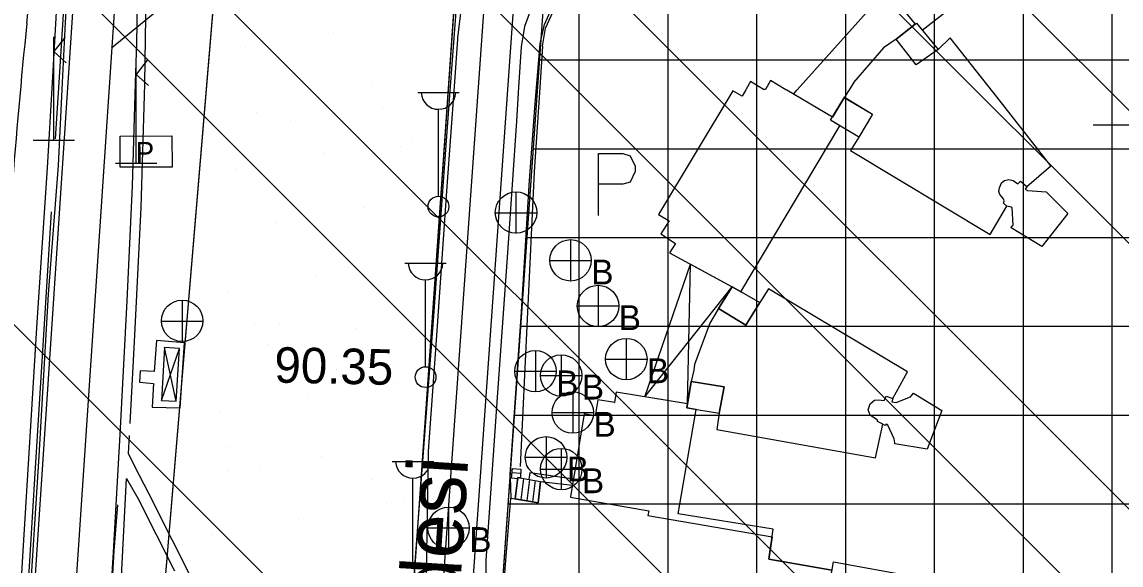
# Model space of a CAD drawing. Extents: x 417995 to 421451, y 4454518 to 4458015.
# Drawn here: x 420306.6 to 420492.2, y 4456425.7 to 4456517.4 of the extents above; entities that cross this region are included whole.
import ezdxf

# ---------------------------------------------------------------- set-up
doc = ezdxf.new("R2010")
doc.units = 0
for name, color, linetype in [('ADAKENARI', 7, 'Continuous'), ('B_Betonzemin', 7, 'Continuous'), ('B_Imalat', 7, 'Continuous'), ('B_Merdiven', 7, 'Continuous'), ('B_Sundurma', 7, 'Continuous'), ('B_Teras', 7, 'Continuous'), ('KALDIRIM_FAT', 7, 'Continuous'), ('P_Grid', 7, 'Continuous'), ('PL_AYA_PARK_DINLENME', 7, 'Continuous'), ('PL_TİCARET', 7, 'Continuous'), ('RAYLI_TOPLU_TAŞIMA_HATTI', 7, 'Continuous'), ('S_Cad_Sok_Lambasi', 7, 'Continuous'), ('S_Kara_Demy_Trafik_Sinyal', 7, 'Continuous'), ('S_Otopark', 7, 'Continuous'), ('S_Pano', 7, 'Continuous'), ('S_Rogar_Kapagi', 7, 'Continuous'), ('S_Rogar_Kapagi_Buski', 7, 'Continuous'), ('Sinir_Duvar_tek_tarafa_ait', 7, 'Continuous'), ('Sinir_Ist_Duvari', 7, 'Continuous'), ('Sinir_Parmaklik_bir_taraf', 7, 'Continuous'), ('Sinir_Tel_bir_taraf', 7, 'Continuous'), ('SN_TR_SIVILASMA', 7, 'Continuous'), ('TRFAT_PARKALANI', 7, 'Continuous'), ('TRFAT_TİCARET', 7, 'Continuous'), ('Y_Cadde_Yol', 7, 'Continuous'), ('Y_Kot_Noktasi', 7, 'Continuous'), ('Yol_Insaat', 7, 'Continuous'), ('Yol_Kaldirim_kenari_bordurtasi', 7, 'Continuous'), ('Yol_Sose', 7, 'Continuous')]:
    doc.layers.add(name, color=color, linetype=linetype)

msp = doc.modelspace()

# ---------------------------------------------------------------- linework, layer by layer
at = {"layer": 'ADAKENARI'}
for p, q in [((420327.09, 4456379.2), (420340.63, 4456540.91)), ((420380.73, 4456537.18), (420369.47, 4456376.76)), ((420385.69, 4456393.42), (420394.63, 4456520.03))]:
    msp.add_line(p, q, dxfattribs=at)
at = {"layer": 'B_Betonzemin'}
for points in [[(420326.52, 4456458.44), (420326.41, 4456456.54), (420328.76, 4456456.33), (420328.56, 4456452.31), (420333.29, 4456452.21), (420334.02, 4456463.18), (420329.28, 4456463.58)], [(420329.28, 4456463.58), (420328.9, 4456458.36), (420326.52, 4456458.44)]]:
    msp.add_lwpolyline(points, dxfattribs=at)
at = {"layer": 'B_Imalat'}
msp.add_lwpolyline([(420449.68, 4456526.48), (420457.39, 4456517.01), (420454.19, 4456514.51), (420452.09, 4456513), (420446.99, 4456507.16), (420446.99, 4456507.13), (420446.19, 4456505.84), (420446.14, 4456505.77), (420445.47, 4456504.69), (420443.45, 4456501.3), (420435.71, 4456505.88), (420435.58, 4456505.95), (420432.97, 4456507.5), (420432.12, 4456505.99), (420431.8, 4456505.99), (420429.58, 4456507.36), (420428.85, 4456506.02), (420428.81, 4456505.95), (420428.22, 4456504.87), (420426.63, 4456505.75), (420414.08, 4456484.89), (420415.86, 4456483.82), (420414.44, 4456481.6), (420416.91, 4456479.96), (420415.94, 4456478.41), (420426.51, 4456472.66), (420424.18, 4456469), (420422.72, 4456466.54), (420422.72, 4456466.54), (420420.12, 4456459.55), (420420.13, 4456459.51), (420420.02, 4456458.59), (420419.59, 4456456.66), (420418.98, 4456452.9), (420406.93, 4456454.89), (420406.65, 4456453.14), (420406.66, 4456453.1), (420403.81, 4456453.55), (420403.36, 4456450.85), (420401.52, 4456451.18), (420401.52, 4456451.18), (420399.2, 4456437.18), (420399.2, 4456437.1), (420412.42, 4456434.83), (420412.26, 4456434.03), (420412.26, 4456434.03), (420433.24, 4456430.4), (420432.7, 4456426.66), (420443.36, 4456424.79)], dxfattribs=at)
at = {"layer": 'B_Merdiven'}
for p, q in [((420389.35, 4456441.3), (420390.77, 4456441.2)), ((420389.91, 4456436.84), (420390.36, 4456440.46)), ((420390.89, 4456436.67), (420391.34, 4456440.28)), ((420391.88, 4456436.49), (420392.33, 4456440.1)), ((420392.86, 4456436.32), (420393.31, 4456439.92))]:
    msp.add_line(p, q, dxfattribs=at)
for points in [[(420389.23, 4456440.31), (420389.42, 4456441.97), (420390.8, 4456441.84), (420390.73, 4456440.39), (420390.32, 4456440.47), (420390.29, 4456440.23)], [(420389.86, 4456436.85), (420390.32, 4456440.47), (420394.12, 4456439.78), (420393.71, 4456436.17)]]:
    msp.add_lwpolyline(points, close=True, dxfattribs=at)
at = {"layer": 'B_Sundurma'}
for p, q in [((420418.98, 4456452.9), (420419.48, 4456476.48)), ((420411.75, 4456454.09), (420426.51, 4456472.66)), ((420332.62, 4456453.32), (420330.63, 4456462.43)), ((420330.11, 4456453.44), (420333.16, 4456462.24))]:
    msp.add_line(p, q, dxfattribs=at)
for points in [[(420419.48, 4456476.48), (420426.51, 4456472.66), (420424.18, 4456469), (420422.72, 4456466.54), (420420.12, 4456459.55), (420420.13, 4456459.51), (420420.02, 4456458.59), (420419.59, 4456456.66), (420418.98, 4456452.9), (420411.75, 4456454.09)], [(420330.63, 4456462.43), (420330.11, 4456453.44), (420332.62, 4456453.32), (420333.16, 4456462.24)]]:
    msp.add_lwpolyline(points, close=True, dxfattribs=at)
at = {"layer": 'B_Teras'}
msp.add_lwpolyline([(420443.36, 4456424.79), (420432.7, 4456426.66), (420432.7, 4456426.66), (420433.43, 4456431.73), (420417.38, 4456434.33), (420417.38, 4456434.33), (420420.43, 4456451.96), (420418.87, 4456452.21), (420419.59, 4456456.66), (420425.13, 4456455.74), (420424.3, 4456451.34), (420423.92, 4456448.55), (420450.74, 4456443.77), (420450.74, 4456443.77), (420451.97, 4456449.44), (420451.05, 4456449.89), (420451.07, 4456450.12), (420449.82, 4456450.95), (420449.47, 4456451.86), (420449.8, 4456452.91), (420450.57, 4456453.5), (420451.18, 4456453.58), (420452.17, 4456453.44), (420452.52, 4456454.18), (420453.62, 4456453.82), (420456.14, 4456458.31), (420432.62, 4456472.29), (420432.62, 4456472.29), (420431.18, 4456470), (420428.84, 4456466.19), (420424.18, 4456469), (420426.51, 4456472.66), (420427.97, 4456471.83), (420444.68, 4456499.86), (420443.14, 4456500.78), (420445.47, 4456504.69), (420450.18, 4456501.81), (420447.88, 4456497.96), (420446.51, 4456495.68), (420470.07, 4456481.51), (420470.07, 4456481.51), (420472.92, 4456486.26), (420472.34, 4456486.81), (420472.46, 4456487.21), (420472.36, 4456487.52), (420471.72, 4456488.25), (420471.55, 4456488.76), (420471.65, 4456489.4), (420472.01, 4456490.24), (420472.51, 4456490.63), (420473.23, 4456490.78), (420473.97, 4456490.59), (420474.74, 4456490.05), (420475.21, 4456490.52), (420476.27, 4456489.62), (420480.32, 4456493.09), (420470.58, 4456505.51), (420470.53, 4456505.58), (420463.35, 4456514.74), (420461.32, 4456512.73), (420457.57, 4456510.15), (420454.19, 4456514.51), (420457.63, 4456517.2), (420458.62, 4456516.02), (420484.26, 4456536.08)], dxfattribs=at)
for points in [[(420454.19, 4456514.51), (420457.63, 4456517.2), (420457.66, 4456517.18), (420461.32, 4456512.73), (420461.3, 4456512.72), (420457.57, 4456510.15)], [(420445.47, 4456504.69), (420445.44, 4456504.64), (420450.18, 4456501.81), (420447.88, 4456497.96), (420447.75, 4456498.03), (420443.14, 4456500.78)], [(420473.65, 4456482.6), (420473.7, 4456482.87), (420473.95, 4456483.08), (420473.77, 4456485.99), (420473.6, 4456486.13), (420472.92, 4456486.26), (420472.34, 4456486.81), (420472.46, 4456487.21), (420472.36, 4456487.52), (420471.72, 4456488.25), (420471.55, 4456488.76), (420471.65, 4456489.4), (420472.01, 4456490.24), (420472.51, 4456490.63), (420473.23, 4456490.78), (420473.97, 4456490.59), (420474.74, 4456490.05), (420474.75, 4456490.06), (420475.21, 4456490.52), (420476.27, 4456489.62), (420476.27, 4456489.54), (420475.99, 4456489.17), (420476.36, 4456488.92), (420479.55, 4456488.72), (420483.21, 4456485.03), (420478.81, 4456479.47)], [(420424.18, 4456469), (420424.18, 4456469), (420428.84, 4456466.19), (420428.84, 4456466.19), (420431.18, 4456470), (420430.96, 4456470.13), (420426.51, 4456472.66)], [(420419.59, 4456456.66), (420419.59, 4456456.56), (420418.87, 4456452.21), (420418.87, 4456452.21), (420424.3, 4456451.34), (420425.13, 4456455.74)], [(420461.9, 4456451.77), (420459.44, 4456445.21), (420459.42, 4456445.22), (420453.96, 4456446.13), (420453.97, 4456446.29), (420453.88, 4456447), (420452.81, 4456449.29), (420452.49, 4456449.43), (420452.36, 4456449.25), (420451.05, 4456449.89), (420451.07, 4456450.12), (420449.82, 4456450.95), (420449.47, 4456451.86), (420449.8, 4456452.91), (420450.57, 4456453.5), (420451.18, 4456453.58), (420452.17, 4456453.44), (420452.52, 4456454.18), (420453.62, 4456453.82), (420453.48, 4456453.22), (420454.2, 4456453.12), (420456.6, 4456454.09), (420457.12, 4456454.68)], [(420455.67, 4456423.98), (420455.62, 4456423.68), (420454.85, 4456418.08), (420442.53, 4456420.01), (420442.53, 4456420.01), (420443.61, 4456426.18)]]:
    msp.add_lwpolyline(points, close=True, dxfattribs=at)
at = {"layer": 'KALDIRIM_FAT'}
for p, q in [((420370.12, 4457345.92), (420299.04, 4456277.89)), ((420377.11, 4457345.45), (420312.53, 4456375.14)), ((420321.7, 4456513.02), (420332.31, 4456521.76)), ((420374.08, 4456370.91), (420384.65, 4456520.64)), ((420381, 4456398.03), (420389.64, 4456520.29))]:
    msp.add_line(p, q, dxfattribs=at)
at = {"layer": 'P_Grid'}
msp.add_line((420487.5, 4456500), (420496.88, 4456500), dxfattribs=at)
at = {"layer": 'PL_AYA_PARK_DINLENME'}
msp.add_lwpolyline([(420327.09, 4456379.2), (420340.63, 4456540.91), (420340.63, 4456540.91), (420342.63, 4456574.69), (420354.57, 4456572.25), (420362.27, 4456570.65), (420359.89, 4456539.15), (420380.73, 4456537.18), (420369.47, 4456376.76), (420369.2, 4456372.87), (420368.81, 4456370.29), (420368.02, 4456367.8), (420366.85, 4456365.47), (420365.33, 4456363.35), (420363.5, 4456361.5), (420361.4, 4456359.95), (420359.08, 4456358.76), (420356.6, 4456357.95), (420354.03, 4456357.53), (420351.42, 4456357.53), (420335.97, 4456358.72), (420326.05, 4456366.7)], close=True, dxfattribs=at)
at = {"layer": 'PL_TİCARET'}
msp.add_lwpolyline([(420623.45, 4456037.14), (420640, 4456310.1), (420637.88, 4456323.02), (420634.68, 4456327.8), (420629.47, 4456331.61), (420628.47, 4456331.87), (420624.59, 4456333.76), (420621.4, 4456334.69), (420462.71, 4456344.9), (420462.86, 4456348.74), (420454.39, 4456348.66), (420437.97, 4456349.54), (420422.37, 4456351.96), (420413.66, 4456354.19), (420405.54, 4456357.63), (420398.67, 4456362.62), (420394.62, 4456367.08), (420390.97, 4456372.75), (420388.74, 4456379.85), (420385.69, 4456393.42), (420394.63, 4456520.03)], dxfattribs=at)
at = {"layer": 'RAYLI_TOPLU_TAŞIMA_HATTI'}
msp.add_line((420307.36, 4456517.18), (420311.28, 4456555.52), dxfattribs=at)
msp.add_arc((421401.66, 4456405.27), 1100, 174.16076, 177.12759, dxfattribs=at)
at = {"layer": 'S_Cad_Sok_Lambasi'}
for p, q in [((420373.4, 4456505.46), (420380.4, 4456505.46)), ((420376.9, 4456487.96), (420376.9, 4456502.64)), ((420371.22, 4456476.65), (420378.22, 4456476.65)), ((420374.72, 4456459.15), (420374.72, 4456473.82)), ((420369.09, 4456443.16), (420376.09, 4456443.16)), ((420372.59, 4456425.66), (420372.59, 4456440.34))]:
    msp.add_line(p, q, dxfattribs=at)
for centre in [(420376.9, 4456486.21), (420374.72, 4456457.4)]:
    msp.add_circle(centre, 1.75, dxfattribs=at)
for centre in [(420376.9, 4456505.57), (420374.72, 4456476.75), (420372.59, 4456443.27)]:
    msp.add_arc(centre, 2.93, 183.298, 356.9072, dxfattribs=at)
at = {"layer": 'S_Kara_Demy_Trafik_Sinyal'}
for p, q in [((420311.95, 4456497.41), (420311.95, 4456514.91)), ((420313.81, 4456514.76), (420311.95, 4456512.38)), ((420311.95, 4456512.38), (420314.03, 4456510.51)), ((420325.83, 4456493.57), (420325.83, 4456511.07)), ((420327.69, 4456510.92), (420325.83, 4456508.54)), ((420325.83, 4456508.54), (420327.9, 4456506.67)), ((420308.45, 4456497.41), (420315.45, 4456497.41)), ((420322.33, 4456493.57), (420329.33, 4456493.57))]:
    msp.add_line(p, q, dxfattribs=at)
at = {"layer": 'S_Otopark'}
for points in [[(420403.95, 4456495.18), (420408.05, 4456495.18)], [(420403.95, 4456484.68), (420403.95, 4456495.18)], [(420408.05, 4456495.18), (420409.27, 4456494.76), (420410.11, 4456493.04), (420410.11, 4456492.13), (420409.27, 4456490.35), (420408.05, 4456490)], [(420408.05, 4456490), (420403.95, 4456490)]]:
    msp.add_lwpolyline(points, dxfattribs=at)
at = {"layer": 'S_Pano'}
msp.add_lwpolyline([(420323.14, 4456498.11), (420331.89, 4456498.14), (420331.91, 4456492.89), (420323.16, 4456492.86)], close=True, dxfattribs=at)
at = {"layer": 'S_Rogar_Kapagi'}
for p, q in [((420390.05, 4456481.67), (420390.05, 4456488.67)), ((420386.48, 4456485.13), (420393.48, 4456485.13)), ((420333.66, 4456463.37), (420333.66, 4456470.37)), ((420330.09, 4456466.84), (420337.09, 4456466.84))]:
    msp.add_line(p, q, dxfattribs=at)
for centre in [(420390, 4456485.2), (420333.61, 4456466.9)]:
    msp.add_circle(centre, 3.5, dxfattribs=at)
at = {"layer": 'S_Rogar_Kapagi_Buski'}
for p, q in [((420399.21, 4456480.63), (420399.21, 4456473.63)), ((420395.71, 4456477.13), (420402.71, 4456477.13)), ((420403.85, 4456472.92), (420403.85, 4456465.92)), ((420400.35, 4456469.42), (420407.35, 4456469.42)), ((420408.62, 4456463.95), (420408.62, 4456456.95)), ((420393.28, 4456461.9), (420393.28, 4456454.9)), ((420397.62, 4456461.19), (420397.62, 4456454.19)), ((420405.12, 4456460.45), (420412.12, 4456460.45)), ((420389.78, 4456458.4), (420396.78, 4456458.4)), ((420394.12, 4456457.69), (420401.12, 4456457.69)), ((420399.59, 4456454.91), (420399.59, 4456447.91)), ((420396.09, 4456451.41), (420403.09, 4456451.41)), ((420395.07, 4456447.36), (420395.07, 4456440.36)), ((420391.57, 4456443.86), (420398.57, 4456443.86)), ((420397.64, 4456445.37), (420397.64, 4456438.37)), ((420394.14, 4456441.87), (420401.14, 4456441.87)), ((420378.6, 4456435.43), (420378.6, 4456428.43)), ((420375.1, 4456431.93), (420382.1, 4456431.93))]:
    msp.add_line(p, q, dxfattribs=at)
for centre in [(420399.21, 4456477.13), (420403.85, 4456469.42), (420408.62, 4456460.45), (420393.28, 4456458.4), (420397.62, 4456457.69), (420399.59, 4456451.41), (420395.07, 4456443.86), (420397.64, 4456441.87), (420378.6, 4456431.93)]:
    msp.add_circle(centre, 3.5, dxfattribs=at)
at = {"layer": 'Sinir_Duvar_tek_tarafa_ait'}
for points in [[(420314.46, 4456533.9), (420312.78, 4456507.17)], [(420312.78, 4456507.17), (420312.18, 4456497.68)], [(420311.5, 4456485.32), (420308.68, 4456440.23), (420306.16, 4456398.65), (420304.25, 4456367.25), (420301.77, 4456327.14), (420300.34, 4456304.24)]]:
    msp.add_lwpolyline(points, dxfattribs=at)
at = {"layer": 'Sinir_Ist_Duvari'}
for points in [[(420437.5, 4456505.93), (420452.61, 4456522.88)], [(420380, 4456521.39), (420378.9, 4456506.48)], [(420378.9, 4456506.48), (420377.83, 4456491.97), (420376.06, 4456467.77), (420374.2, 4456443.18), (420372.39, 4456419.48), (420370.45, 4456390.9), (420369.46, 4456376.15)], [(420378.85, 4456506.55), (420378.85, 4456506.55)], [(420378.85, 4456506.55), (420378.85, 4456506.48)], [(420436.9, 4456505.26), (420437.43, 4456505.86)], [(420437.43, 4456505.86), (420437.5, 4456505.93)], [(420388.99, 4456440.56), (420389.01, 4456440.97), (420390.76, 4456466), (420390.84, 4456467.53), (420392.21, 4456489.77), (420392.21, 4456489.83), (420393.17, 4456502.91)], [(420392.23, 4456440.12), (420392.37, 4456441.32), (420399.7, 4456440.2)], [(420393.55, 4456419.99), (420387.79, 4456420.11), (420389.14, 4456436.98), (420393.71, 4456436.17), (420394.12, 4456439.78)], [(420394.12, 4456439.78), (420399.53, 4456439.17)]]:
    msp.add_lwpolyline(points, dxfattribs=at)
at = {"layer": 'Sinir_Parmaklik_bir_taraf'}
msp.add_lwpolyline([(420352.67, 4456353.58), (420347.63, 4456353.57), (420336.4, 4456354.58), (420334.12, 4456354.82), (420328.97, 4456357.17), (420325.71, 4456359.73), (420323.17, 4456362.66), (420321.46, 4456365.5), (420319.97, 4456369.43), (420319.47, 4456372.15), (420319.08, 4456376.65), (420319.59, 4456384.7), (420320.77, 4456404.44), (420322.14, 4456428.04), (420322.72, 4456435.84)], dxfattribs=at)
at = {"layer": 'Sinir_Tel_bir_taraf'}
for points in [[(420394.06, 4456513.74), (420394.79, 4456516.96), (420396.47, 4456520.73), (420398.86, 4456523.79), (420402.82, 4456526.65), (420423.37, 4456536.86)], [(420393.45, 4456506.32), (420394.06, 4456513.74)], [(420393.17, 4456502.91), (420393.45, 4456506.32)]]:
    msp.add_lwpolyline(points, dxfattribs=at)
at = {"layer": 'SN_TR_SIVILASMA'}
for p, q in [((421273.94, 4455722.03), (420248.84, 4456747.14)), ((421273.71, 4455699.81), (420266.8, 4456706.72)), ((421273.25, 4455655.37), (420276.01, 4456652.61)), ((421273.02, 4455633.15), (420276.28, 4456629.89)), ((421272.55, 4455588.71), (420264.03, 4456597.24)), ((421272.32, 4455566.5), (420257.91, 4456580.91)), ((421271.63, 4455499.84), (420239.54, 4456531.93))]:
    msp.add_line(p, q, dxfattribs=at)
at = {"layer": 'TRFAT_PARKALANI'}
for p, q in [((420359.09, 4456515.67), (420359.09, 4456515.67)), ((420344.32, 4456513.06), (420344.32, 4456513.06)), ((420365.75, 4456506.69), (420365.75, 4456506.69)), ((420350.98, 4456504.08), (420350.98, 4456504.08)), ((420346.11, 4456502.11), (420346.11, 4456502.11)), ((420367.53, 4456503.02), (420367.53, 4456503.02)), ((420351.88, 4456500.71), (420351.88, 4456500.71)), ((420372.41, 4456497.71), (420372.41, 4456497.71)), ((420370.45, 4456496.43), (420370.45, 4456496.43)), ((420357.64, 4456495.1), (420357.64, 4456495.1)), ((420342.86, 4456492.5), (420342.86, 4456492.5)), ((420364.3, 4456486.12), (420364.3, 4456486.12)), ((420349.53, 4456483.52), (420349.53, 4456483.52)), ((420348.41, 4456481.01), (420348.41, 4456481.01)), ((420363.18, 4456478.4), (420363.18, 4456478.4)), ((420361.56, 4456475.91), (420361.56, 4456475.91)), ((420370.96, 4456477.14), (420370.96, 4456477.14)), ((420356.19, 4456474.54), (420356.19, 4456474.54)), ((420341.41, 4456471.94), (420341.41, 4456471.94)), ((420345.81, 4456466.24), (420345.81, 4456466.24)), ((420350.07, 4456466.27), (420350.07, 4456466.27)), ((420362.85, 4456465.56), (420362.85, 4456465.56)), ((420348.07, 4456462.96), (420348.07, 4456462.96)), ((420359.71, 4456458.71), (420359.71, 4456458.71)), ((420369.51, 4456456.58), (420369.51, 4456456.58)), ((420374.48, 4456456.1), (420374.48, 4456456.1)), ((420354.73, 4456453.98), (420354.73, 4456453.98)), ((420339.96, 4456451.37), (420339.96, 4456451.37)), ((420341.18, 4456445.76), (420341.18, 4456445.76)), ((420357.11, 4456443.94), (420357.11, 4456443.94)), ((420361.4, 4456445), (420361.4, 4456445)), ((420346.62, 4456442.39), (420346.62, 4456442.39)), ((420341.47, 4456441.62), (420341.47, 4456441.62)), ((420365.52, 4456440.08), (420365.52, 4456440.08)), ((420371.01, 4456436.41), (420371.01, 4456436.41)), ((420368.06, 4456436.02), (420368.06, 4456436.02)), ((420353.28, 4456433.41), (420353.28, 4456433.41)), ((420338.51, 4456430.81), (420338.51, 4456430.81))]:
    msp.add_line(p, q, dxfattribs=at)
at = {"layer": 'TRFAT_TİCARET'}
for p, q in [((420490.69, 4456343.1), (420490.69, 4456569.86)), ((420475.69, 4456344.06), (420475.69, 4456562.5)), ((420460.69, 4456348.72), (420460.69, 4456555.15)), ((420445.69, 4456349.12), (420445.69, 4456547.79)), ((420430.69, 4456350.67), (420430.69, 4456540.44)), ((420415.69, 4456353.67), (420415.69, 4456533.08)), ((420400.69, 4456361.15), (420400.69, 4456525.73)), ((420393.99, 4456510.99), (420740.81, 4456510.99)), ((420392.93, 4456495.99), (420741.56, 4456495.99)), ((420391.87, 4456480.99), (420740.53, 4456480.99)), ((420390.81, 4456465.99), (420739.51, 4456465.99)), ((420389.76, 4456450.99), (420738.49, 4456450.99)), ((420388.7, 4456435.99), (420737.47, 4456435.99))]:
    msp.add_line(p, q, dxfattribs=at)
at = {"layer": 'Yol_Insaat'}
for points in [[(420313.2, 4456533.98), (420311.65, 4456507.19)], [(420311.65, 4456507.19), (420310.81, 4456492.77), (420309.04, 4456466.64), (420306.65, 4456427.13), (420304.84, 4456396.34), (420302.72, 4456361.66), (420300.32, 4456324.62), (420299.34, 4456304.02), (420298.49, 4456284.56)]]:
    msp.add_lwpolyline(points, dxfattribs=at)
at = {"layer": 'Yol_Kaldirim_kenari_bordurtasi'}
for points in [[(420327.94, 4456539.92), (420327.52, 4456525.84), (420327.23, 4456507.02)], [(420327.23, 4456507.02), (420327.2, 4456504.98), (420326.61, 4456486.08), (420325.57, 4456464.51), (420324.75, 4456449.55)], [(420324.65, 4456447.56), (420324.48, 4456444.48), (420326.37, 4456440.86), (420327.92, 4456437.83), (420335.93, 4456421.93), (420346.69, 4456400.67), (420358.79, 4456376.94), (420369.65, 4456376.14)], [(420323.18, 4456420.38), (420324.2, 4456440.27), (420326.11, 4456436.97), (420332.33, 4456424.67)], [(420388.99, 4456440.56), (420389.14, 4456436.98)]]:
    msp.add_lwpolyline(points, dxfattribs=at)
at = {"layer": 'Yol_Sose'}
for points in [[(420313.42, 4456507.17), (420313.93, 4456517.28), (420315.33, 4456540.61)], [(420326.33, 4456539.92), (420325.88, 4456513.94), (420325.68, 4456507.04)], [(420394.46, 4456513.31), (420394.99, 4456516.35), (420396.58, 4456519.76), (420398.9, 4456522.55), (420403.72, 4456526.46), (420423.38, 4456536.1), (420423.54, 4456536.54), (420422.14, 4456539.16), (420421.45, 4456538.8), (420409.94, 4456533.24), (420400.51, 4456528.57), (420397.12, 4456526.28), (420394.59, 4456523.42), (420392.96, 4456520.76), (420391.43, 4456516.61)], [(420380.15, 4456514.51), (420380.19, 4456514.7), (420381.11, 4456522.68), (420382.17, 4456530.6), (420389.33, 4456532.08), (420389.28, 4456532.33)], [(420391.43, 4456516.61), (420390.84, 4456513.19), (420390.43, 4456506.36)], [(420379.58, 4456506.47), (420380.15, 4456514.51)], [(420394.46, 4456513.31), (420394.01, 4456506.32)], [(420300.26, 4456283.95), (420301.25, 4456300.9), (420302.09, 4456320.86), (420303.41, 4456343.89), (420304.8, 4456367.92), (420306.42, 4456393.29), (420307.71, 4456416.68), (420309.45, 4456444.06), (420311.03, 4456471.44), (420312.72, 4456493.17), (420313.42, 4456507.17)], [(420325.68, 4456507.04), (420325.19, 4456489.68)], [(420374.87, 4456424.24), (420375.24, 4456444.88), (420376.67, 4456465.2), (420378.37, 4456489.61), (420379.58, 4456506.47)], [(420390.43, 4456506.36), (420390.1, 4456500.66), (420388.62, 4456479.25)], [(420394.01, 4456506.32), (420393.09, 4456492.06), (420390.67, 4456442.29)], [(420325.19, 4456489.68), (420324.24, 4456470.29), (420323.07, 4456447.69)], [(420388.62, 4456479.25), (420386.78, 4456453.17), (420384.9, 4456426.45), (420384.87, 4456418.8), (420385.62, 4456417.81), (420386.52, 4456417.4), (420390.18, 4456417.29), (420394.11, 4456417.51), (420394.48, 4456418.04), (420394.63, 4456418.82), (420394.66, 4456419.82)], [(420323.07, 4456447.69), (420321.95, 4456427.82), (420320.38, 4456402.04)]]:
    msp.add_lwpolyline(points, dxfattribs=at)

# ---------------------------------------------------------------- texts
at = {"layer": 'S_Pano'}
msp.add_text('P', height=3.5, rotation=0.1826, dxfattribs=at).set_placement((420325.76, 4456493.63))
at = {"layer": 'S_Rogar_Kapagi_Buski'}
for p in [(420402.71, 4456473.06), (420407.35, 4456465.35), (420412.12, 4456456.38), (420396.78, 4456454.33), (420401.12, 4456453.62), (420403.09, 4456447.34), (420398.57, 4456439.79), (420401.14, 4456437.8), (420382.1, 4456427.86)]:
    msp.add_text('B', height=4.2, dxfattribs=at).set_placement(p)
at = {"layer": 'Y_Cadde_Yol'}
msp.add_text('Fuar Caddesi', height=10, rotation=86.4497, dxfattribs=at).set_placement((420376.96, 4456363.51))
at = {"layer": 'Y_Kot_Noktasi'}
msp.add_text('90.35', height=6, rotation=358.8289, dxfattribs=at).set_placement((420349.14, 4456456.49))

doc.saveas('drawing.dxf')
